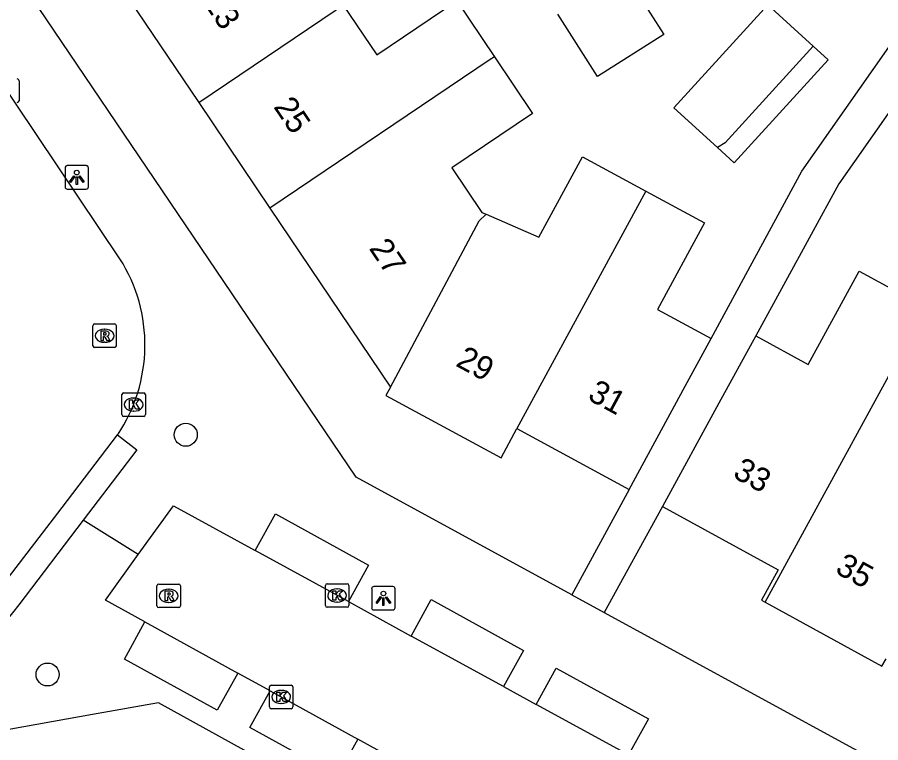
# Model space of a CAD drawing. Extents: x 158352 to 159489, y 383828 to 384597.
# Drawn here: x 158842 to 158878.73, y 384075.57 to 384106.43 of the extents above; entities that cross this region are included whole.
import ezdxf

# ---------------------------------------------------------------- set-up
doc = ezdxf.new("R2010")
doc.units = 0
for name, color, linetype in [('IMGEO_Boom', 7, 'Continuous'), ('IMGEO_Kolk', 7, 'Continuous'), ('IMGEO_Lichtpunt', 7, 'Continuous'), ('IMGEO_Pand', 7, 'Continuous'), ('IMGEO_Pand_nummerreeks', 7, 'Continuous'), ('IMGEO_Rijbaan_lokaal_open', 7, 'Continuous'), ('IMGEO_Rioolput', 7, 'Continuous'), ('IMGEO_Voetpad_open', 7, 'Continuous')]:
    doc.layers.add(name, color=color, linetype=linetype)

msp = doc.modelspace()

# ---------------------------------------------------------------- linework, layer by layer
at = {"layer": 'IMGEO_Boom'}
for centre in [(158849.17, 384088.668), (158843.291, 384078.471)]:
    msp.add_circle(centre, 0.489, dxfattribs=at)
at = {"layer": 'IMGEO_Kolk'}
for p, q in [((158842.076, 384103.729), (158842.076, 384102.877)), ((158846.453, 384089.525), (158846.453, 384090.377)), ((158846.528, 384090.451), (158847.38, 384090.451)), ((158847.454, 384090.377), (158847.454, 384089.525)), ((158846.941, 384090.231), (158846.966, 384090.231)), ((158846.964, 384089.671), (158846.939, 384089.671)), ((158847.38, 384089.451), (158846.528, 384089.451)), ((158855.107, 384081.408), (158855.107, 384082.26)), ((158855.182, 384082.334), (158856.034, 384082.334)), ((158856.108, 384082.26), (158856.108, 384081.408)), ((158855.595, 384082.114), (158855.62, 384082.114)), ((158855.618, 384081.554), (158855.593, 384081.554)), ((158856.034, 384081.334), (158855.182, 384081.334)), ((158852.729, 384077.091), (158852.729, 384077.943)), ((158852.804, 384078.017), (158853.656, 384078.017)), ((158853.217, 384077.797), (158853.242, 384077.797)), ((158853.73, 384077.943), (158853.73, 384077.091)), ((158853.24, 384077.237), (158853.215, 384077.237)), ((158853.656, 384077.017), (158852.804, 384077.017))]:
    msp.add_line(p, q, dxfattribs=at)
for points in [[(158842.076, 384103.729), (158842.076, 384102.877)], [(158846.453, 384089.525), (158846.453, 384090.377)], [(158846.528, 384090.451), (158847.38, 384090.451)], [(158847.454, 384090.377), (158847.454, 384089.525)], [(158846.774, 384090.151), (158846.897, 384090.151), (158846.897, 384090), (158847.027, 384090.151), (158847.191, 384090.151), (158847.045, 384090), (158847.198, 384089.751), (158847.046, 384089.751), (158846.961, 384089.915), (158846.897, 384089.848), (158846.897, 384089.751), (158846.774, 384089.751), (158846.774, 384090.151)], [(158847.38, 384089.451), (158846.528, 384089.451)], [(158855.107, 384081.408), (158855.107, 384082.26)], [(158855.182, 384082.334), (158856.034, 384082.334)], [(158856.108, 384082.26), (158856.108, 384081.408)], [(158855.428, 384082.034), (158855.551, 384082.034), (158855.551, 384081.883), (158855.681, 384082.034), (158855.845, 384082.034), (158855.699, 384081.883), (158855.852, 384081.634), (158855.7, 384081.634), (158855.615, 384081.798), (158855.551, 384081.731), (158855.551, 384081.634), (158855.428, 384081.634), (158855.428, 384082.034)], [(158856.034, 384081.334), (158855.182, 384081.334)], [(158852.729, 384077.091), (158852.729, 384077.943)], [(158852.804, 384078.017), (158853.656, 384078.017)], [(158853.73, 384077.943), (158853.73, 384077.091)], [(158853.05, 384077.717), (158853.173, 384077.717), (158853.173, 384077.566), (158853.303, 384077.717), (158853.467, 384077.717), (158853.321, 384077.566), (158853.474, 384077.317), (158853.322, 384077.317), (158853.237, 384077.481), (158853.173, 384077.414), (158853.173, 384077.317), (158853.05, 384077.317), (158853.05, 384077.717)], [(158853.656, 384077.017), (158852.804, 384077.017)]]:
    msp.add_lwpolyline(points, dxfattribs=at)
for centre, start, end in [((158842, 384103.727), 1.552, 88.448), ((158842, 384103.727), 1.552, 88.448), ((158842, 384102.879), 271.552, 358.448), ((158842, 384102.879), 271.552, 358.448), ((158846.53, 384090.375), 91.552, 178.448), ((158846.53, 384090.375), 91.552, 178.448), ((158847.378, 384090.375), 1.552, 88.448), ((158847.378, 384090.375), 1.552, 88.448), ((158846.53, 384089.527), 181.552, 268.448), ((158846.53, 384089.527), 181.552, 268.448), ((158847.378, 384089.527), 271.552, 358.448), ((158847.378, 384089.527), 271.552, 358.448), ((158855.184, 384082.258), 91.552, 178.448), ((158855.184, 384082.258), 91.552, 178.448), ((158856.032, 384082.258), 1.552, 88.448), ((158856.032, 384082.258), 1.552, 88.448), ((158855.184, 384081.41), 181.552, 268.448), ((158855.184, 384081.41), 181.552, 268.448), ((158856.032, 384081.41), 271.552, 358.448), ((158856.032, 384081.41), 271.552, 358.448), ((158852.806, 384077.941), 91.552, 178.448), ((158852.806, 384077.941), 91.552, 178.448), ((158853.654, 384077.941), 1.552, 88.448), ((158853.654, 384077.941), 1.552, 88.448), ((158852.806, 384077.093), 181.552, 268.448), ((158852.806, 384077.093), 181.552, 268.448), ((158853.654, 384077.093), 271.552, 358.448), ((158853.654, 384077.093), 271.552, 358.448)]:
    msp.add_arc(centre, 0.0765, start, end, dxfattribs=at)
for centre, major_axis, ratio, start_param, end_param in [((158846.94, 384089.951), (-0.387, 0.002), 0.722429, 4.712389, 7.853982), ((158846.965, 384089.951), (-0.39, 0.002), 0.717154, 1.570796, 4.712389), ((158855.594, 384081.834), (-0.387, 0.002), 0.722429, 4.712389, 7.853982), ((158855.619, 384081.834), (-0.39, 0.002), 0.717154, 1.570796, 4.712389), ((158853.216, 384077.517), (-0.387, 0.002), 0.722429, 4.712389, 7.853982), ((158853.241, 384077.517), (-0.39, 0.002), 0.717154, 1.570796, 4.712389)]:
    msp.add_ellipse(centre, major_axis=major_axis, ratio=ratio, start_param=start_param, end_param=end_param, dxfattribs=at)
at = {"layer": 'IMGEO_Lichtpunt'}
for p, q in [((158844.035, 384100.021), (158844.035, 384099.214)), ((158844.035, 384100.021), (158844.035, 384099.214)), ((158844.937, 384100.116), (158844.129, 384100.116)), ((158844.937, 384100.116), (158844.129, 384100.116)), ((158845.031, 384099.214), (158845.031, 384100.021)), ((158845.031, 384099.214), (158845.031, 384100.021)), ((158844.129, 384099.12), (158844.937, 384099.12)), ((158844.129, 384099.12), (158844.937, 384099.12)), ((158857.98, 384082.213), (158857.172, 384082.213)), ((158857.98, 384082.213), (158857.172, 384082.213)), ((158857.078, 384082.118), (158857.078, 384081.311)), ((158857.078, 384082.118), (158857.078, 384081.311)), ((158858.074, 384081.311), (158858.074, 384082.118)), ((158858.074, 384081.311), (158858.074, 384082.118)), ((158857.172, 384081.217), (158857.98, 384081.217)), ((158857.172, 384081.217), (158857.98, 384081.217))]:
    msp.add_line(p, q, dxfattribs=at)
for points in [[(158844.409, 384099.685), (158844.448, 384099.657), (158844.26, 384099.395), (158844.222, 384099.422), (158844.409, 384099.685)], [(158844.511, 384099.637), (158844.558, 384099.637), (158844.558, 384099.315), (158844.511, 384099.315), (158844.511, 384099.637)], [(158844.621, 384099.657), (158844.659, 384099.684), (158844.846, 384099.422), (158844.807, 384099.394), (158844.621, 384099.657)], [(158857.452, 384081.782), (158857.491, 384081.754), (158857.303, 384081.492), (158857.265, 384081.519), (158857.452, 384081.782)], [(158857.554, 384081.734), (158857.601, 384081.734), (158857.601, 384081.412), (158857.554, 384081.412), (158857.554, 384081.734)], [(158857.664, 384081.754), (158857.702, 384081.781), (158857.889, 384081.519), (158857.85, 384081.491), (158857.664, 384081.754)]]:
    msp.add_lwpolyline(points, dxfattribs=at)
for centre in [(158844.534, 384099.819), (158857.577, 384081.916)]:
    msp.add_circle(centre, 0.0994, dxfattribs=at)
for centre, start, end in [((158844.129, 384100.021), 90, 180), ((158844.129, 384100.021), 90, 180), ((158844.937, 384100.021), 0, 90), ((158844.937, 384100.021), 0, 90), ((158844.129, 384099.214), 180, 270), ((158844.129, 384099.214), 180, 270), ((158844.937, 384099.214), 270, 0), ((158844.937, 384099.214), 270, 360), ((158857.172, 384082.118), 90, 180), ((158857.172, 384082.118), 90, 180), ((158857.98, 384082.118), 0, 90), ((158857.98, 384082.118), 0, 90), ((158857.172, 384081.311), 180, 270), ((158857.172, 384081.311), 180, 270), ((158857.98, 384081.311), 270, 0), ((158857.98, 384081.311), 270, 360)]:
    msp.add_arc(centre, 0.0946, start, end, dxfattribs=at)
at = {"layer": 'IMGEO_Pand'}
for points in [[(158867.767, 384108.433), (158869.507, 384105.698), (158866.685, 384103.903), (158864.993, 384106.563)], [(158846.757, 384107.195), (158849.719, 384102.801)], [(158849.719, 384102.801), (158855.521, 384106.712), (158855.868, 384106.946)], [(158855.868, 384106.946), (158857.293, 384104.833), (158860.694, 384107.127), (158862.299, 384104.746)], [(158871.789, 384100.886), (158869.935, 384102.581), (158873.936, 384106.961), (158875.864, 384105.2)], [(158875.864, 384105.2), (158872.118, 384101.087), (158871.789, 384100.886)], [(158875.864, 384105.2), (158876.504, 384104.615), (158872.503, 384100.235), (158871.789, 384100.886)], [(158862.299, 384104.746), (158862.12, 384104.626), (158852.748, 384098.308)], [(158862.299, 384104.746), (158863.921, 384102.34), (158860.483, 384100.022), (158861.759, 384098.128), (158861.946, 384098.047)], [(158849.719, 384102.801), (158852.748, 384098.308)], [(158861.946, 384098.047), (158864.19, 384097.069), (158866.05, 384100.495), (158868.747, 384099.031)], [(158868.747, 384099.031), (158863.257, 384088.93)], [(158868.747, 384099.031), (158871.235, 384097.68), (158869.236, 384093.999), (158871.513, 384092.763)], [(158852.748, 384098.308), (158857.879, 384090.697)], [(158857.879, 384090.697), (158861.648, 384097.772), (158861.946, 384098.047)], [(158873.413, 384092.876), (158875.645, 384091.654), (158877.822, 384095.632), (158880.667, 384094.076)], [(158873.813, 384081.548), (158880.667, 384094.076)], [(158873.413, 384092.876), (158871.846, 384090.01), (158869.446, 384085.623)], [(158868.026, 384086.341), (158870.412, 384090.736), (158871.513, 384092.763)], [(158857.879, 384090.697), (158857.686, 384090.341), (158862.58, 384087.684), (158863.257, 384088.93)], [(158863.257, 384088.93), (158868.026, 384086.341)], [(158869.446, 384085.623), (158874.377, 384082.925), (158873.667, 384081.628), (158873.813, 384081.548)], [(158873.813, 384081.548), (158878.785, 384078.828), (158878.958, 384079.144)]]:
    msp.add_lwpolyline(points, dxfattribs=at)
at = {"layer": 'IMGEO_Rijbaan_lokaal_open'}
for points in [[(158846.369, 384096.156), (158829.599, 384121.155)], [(158840.709, 384081.381), (158841.45, 384082.351), (158843.916, 384085.581), (158846.266, 384088.659)], [(158847.15, 384083.569), (158848.652, 384085.644), (158852.125, 384083.742)], [(158856.09, 384081.571), (158852.125, 384083.742)], [(158847.435, 384080.706), (158845.75, 384081.634), (158847.15, 384083.569)], [(158856.09, 384081.571), (158858.762, 384080.108)], [(158847.435, 384080.706), (158851.384, 384078.533)], [(158862.693, 384077.956), (158858.762, 384080.108)], [(158852.754, 384077.778), (158851.384, 384078.533)], [(158852.754, 384077.778), (158856.486, 384075.723)], [(158862.693, 384077.956), (158864.081, 384077.196)], [(158868.005, 384075.047), (158864.081, 384077.196)], [(158857.855, 384074.969), (158856.486, 384075.723)]]:
    msp.add_lwpolyline(points, dxfattribs=at)
msp.add_arc((158840.577, 384092.486), 6.857, 326.0683, 32.3574, dxfattribs=at)
at = {"layer": 'IMGEO_Rioolput'}
for p, q in [((158845.215, 384092.456), (158845.215, 384093.308)), ((158845.29, 384093.382), (158846.142, 384093.382)), ((158846.216, 384093.308), (158846.216, 384092.456)), ((158845.703, 384093.162), (158845.728, 384093.162)), ((158845.726, 384092.602), (158845.701, 384092.602)), ((158846.142, 384092.382), (158845.29, 384092.382)), ((158847.944, 384081.391), (158847.944, 384082.243)), ((158848.019, 384082.317), (158848.871, 384082.317)), ((158848.945, 384082.243), (158848.945, 384081.391)), ((158848.432, 384082.097), (158848.457, 384082.097)), ((158848.455, 384081.537), (158848.43, 384081.537)), ((158848.871, 384081.317), (158848.019, 384081.317))]:
    msp.add_line(p, q, dxfattribs=at)
for points in [[(158845.215, 384092.456), (158845.215, 384093.308)], [(158845.29, 384093.382), (158846.142, 384093.382)], [(158846.216, 384093.308), (158846.216, 384092.456)], [(158845.804, 384093.08), (158845.552, 384093.082), (158845.552, 384092.682)], [(158845.552, 384092.682), (158845.676, 384092.682), (158845.676, 384092.844), (158845.687, 384092.844)], [(158845.73, 384093.001), (158845.676, 384093.001), (158845.676, 384092.92)], [(158845.676, 384092.92), (158845.728, 384092.92)], [(158845.734, 384092.815), (158845.805, 384092.682), (158845.945, 384092.682), (158845.88, 384092.808)], [(158846.142, 384092.382), (158845.29, 384092.382)], [(158847.944, 384081.391), (158847.944, 384082.243)], [(158848.019, 384082.317), (158848.871, 384082.317)], [(158848.945, 384082.243), (158848.945, 384081.391)], [(158848.533, 384082.015), (158848.281, 384082.017), (158848.281, 384081.617)], [(158848.459, 384081.936), (158848.405, 384081.936), (158848.405, 384081.855)], [(158848.405, 384081.855), (158848.457, 384081.855)], [(158848.281, 384081.617), (158848.405, 384081.617), (158848.405, 384081.779), (158848.416, 384081.779)], [(158848.463, 384081.75), (158848.534, 384081.617), (158848.674, 384081.617), (158848.609, 384081.743)], [(158848.871, 384081.317), (158848.019, 384081.317)]]:
    msp.add_lwpolyline(points, dxfattribs=at)
for centre, radius, start, end in [((158845.292, 384093.306), 0.0765, 91.552, 178.448), ((158845.292, 384093.306), 0.0765, 91.552, 178.448), ((158846.14, 384093.306), 0.0765, 1.552, 88.448), ((158846.14, 384093.306), 0.0765, 1.552, 88.448), ((158845.686, 384092.791), 0.0533, 26.0293, 88.6989), ((158845.712, 384093.109), 0.19, 274.7715, 282.9687), ((158845.736, 384092.905), 0.0964, 77.0061, 93.1865), ((158845.75, 384092.962), 0.0378, 276.6634, 79.6772), ((158845.803, 384092.97), 0.109, 350.3612, 89.416), ((158845.801, 384092.97), 0.112, 277.5842, 350.9817), ((158845.785, 384092.755), 0.108, 29.5134, 73.7905), ((158845.292, 384092.458), 0.0765, 181.552, 268.448), ((158845.292, 384092.458), 0.0765, 181.552, 268.448), ((158846.14, 384092.458), 0.0765, 271.552, 358.448), ((158846.14, 384092.458), 0.0765, 271.552, 358.448), ((158848.021, 384082.241), 0.0765, 91.552, 178.448), ((158848.021, 384082.241), 0.0765, 91.552, 178.448), ((158848.869, 384082.241), 0.0765, 1.552, 88.448), ((158848.869, 384082.241), 0.0765, 1.552, 88.448), ((158848.441, 384082.044), 0.19, 274.7715, 282.9687), ((158848.465, 384081.84), 0.0964, 77.0061, 93.1865), ((158848.479, 384081.897), 0.0378, 276.6634, 79.6772), ((158848.532, 384081.905), 0.109, 350.3612, 89.416), ((158848.53, 384081.905), 0.112, 277.5842, 350.9817), ((158848.514, 384081.69), 0.108, 29.5134, 73.7905), ((158848.415, 384081.726), 0.0533, 26.0293, 88.6989), ((158848.021, 384081.393), 0.0765, 181.552, 268.448), ((158848.021, 384081.393), 0.0765, 181.552, 268.448), ((158848.869, 384081.393), 0.0765, 271.552, 358.448), ((158848.869, 384081.393), 0.0765, 271.552, 358.448)]:
    msp.add_arc(centre, radius, start, end, dxfattribs=at)
for centre, major_axis, ratio, start_param, end_param in [((158845.702, 384092.882), (-0.387, 0.002), 0.722429, 4.712389, 7.853982), ((158845.727, 384092.882), (-0.39, 0.002), 0.717154, 1.570796, 4.712389), ((158848.431, 384081.817), (-0.387, 0.002), 0.722429, 4.712389, 7.853982), ((158848.456, 384081.817), (-0.39, 0.002), 0.717154, 1.570796, 4.712389)]:
    msp.add_ellipse(centre, major_axis=major_axis, ratio=ratio, start_param=start_param, end_param=end_param, dxfattribs=at)
at = {"layer": 'IMGEO_Voetpad_open'}
for points in [[(158865.594, 384081.861), (158856.419, 384086.867), (158834.976, 384118.562)], [(158871.513, 384092.763), (158875.376, 384099.88), (158880.878, 384107.738), (158891.076, 384102.332)], [(158891.076, 384102.332), (158896.539, 384099.436), (158895.588, 384097.676), (158881.147, 384105.332), (158876.954, 384099.344), (158873.413, 384092.876)], [(158846.266, 384088.659), (158847.093, 384088.028), (158844.803, 384085.029)], [(158868.026, 384086.341), (158865.594, 384081.861)], [(158869.446, 384085.623), (158866.975, 384081.108)], [(158852.125, 384083.742), (158852.985, 384085.305), (158856.945, 384083.124), (158856.09, 384081.571)], [(158844.803, 384085.029), (158842.063, 384081.44), (158841.536, 384080.75), (158840.709, 384081.381)], [(158847.15, 384083.569), (158844.803, 384085.029)], [(158865.594, 384081.861), (158866.975, 384081.108)], [(158858.762, 384080.108), (158859.614, 384081.655), (158863.54, 384079.493), (158862.693, 384077.956)], [(158866.975, 384081.108), (158906.994, 384059.275)], [(158851.384, 384078.533), (158850.511, 384076.948), (158846.563, 384079.122), (158847.435, 384080.706)], [(158864.081, 384077.196), (158864.933, 384078.743), (158868.852, 384076.584), (158868.005, 384075.047)], [(158856.486, 384075.723), (158855.628, 384074.165), (158851.896, 384076.22), (158852.754, 384077.778)], [(158848.008, 384077.264), (158845.207, 384076.768), (158841.164, 384076.052), (158841.504, 384074.132), (158846.398, 384074.998), (158847.446, 384075.184), (158851.596, 384072.898), (158852.606, 384074.732), (158848.008, 384077.264)]]:
    msp.add_lwpolyline(points, dxfattribs=at)

# ---------------------------------------------------------------- texts
at = {"layer": 'IMGEO_Pand_nummerreeks'}
for s, rotation, p in [('23', 303.9861, (158849.892, 384107.052)), ('25', 303.9861, (158852.881, 384102.619)), ('27', 303.9861, (158856.941, 384096.597)), ('29', 331.502, (158860.609, 384091.621)), ('31', 331.5033, (158866.217, 384090.19)), ('33', 331.3147, (158872.396, 384086.881)), ('35', 331.3177, (158876.748, 384082.815))]:
    msp.add_text(s, height=1, rotation=rotation, dxfattribs=at).set_placement(p)

doc.saveas('drawing.dxf')
